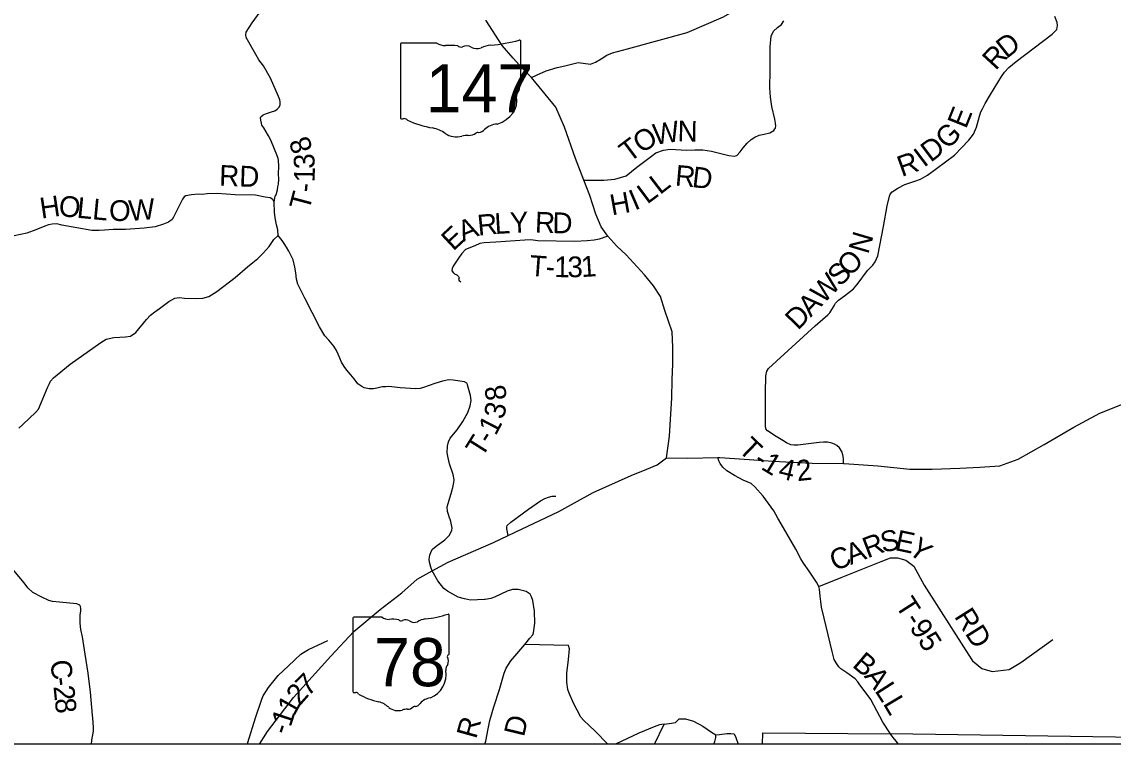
# Model space of a CAD drawing. Extents: x -22 to 431, y -18 to 160.
# Drawn here: x 327.228 to 330.215, y 147.68 to 149.657 of the extents above; entities that cross this region are included whole.
import ezdxf

# ---------------------------------------------------------------- set-up
doc = ezdxf.new("R2010")
doc.units = 0
for name, color, linetype in [('GM_X_Adjacent_County_Text', 7, 'Continuous'), ('GM_X_Airport_Location_Class_2', 7, 'Continuous'), ('GM_X_City_Street', 7, 'Continuous'), ('GM_X_City_Street_Text', 7, 'Continuous'), ('GM_X_County_Road', 7, 'Continuous'), ('GM_X_County_ROW', 7, 'Continuous'), ('GM_X_Major_River_Text', 7, 'Continuous'), ('GM_X_Minor_River_Text', 7, 'Continuous'), ('GM_X_Section', 7, 'Continuous')]:
    doc.layers.add(name, color=color, linetype=linetype)

msp = doc.modelspace()

# ---------------------------------------------------------------- linework, layer by layer
at = {"layer": 'GM_X_Adjacent_County_Text'}
for points in [[(327.2193, 148.5451), (327.2307, 148.5547), (327.266, 148.5891), (327.273, 148.597), (327.2809, 148.6148), (327.2985, 148.6585), (327.3031, 148.6676), (327.3065, 148.6733), (327.3142, 148.6825), (327.36, 148.7198), (327.444, 148.7799), (327.4586, 148.7886), (327.4799, 148.7933), (327.5119, 148.7948), (327.5251, 148.7968), (327.54, 148.8073), (327.5688, 148.8423), (327.5796, 148.854), (327.5916, 148.8636), (327.605, 148.8727), (327.6301, 148.8916), (327.6467, 148.901), (327.659, 148.9027), (327.6727, 148.9013), (327.7048, 148.8998), (327.7232, 148.9013), (327.7395, 148.9056), (327.762, 148.9188), (327.8116, 148.9579), (327.8455, 148.9866), (327.8599, 148.9989), (327.8735, 149.0092), (327.8889, 149.024), (327.9046, 149.0424), (327.9174, 149.0615), (327.9298, 149.0722), (327.9282, 149.0879), (327.9249, 149.1021), (327.9217, 149.1209), (327.9198, 149.1368), (327.9183, 149.1641), (327.9146, 149.171), (327.9077, 149.1755), (327.8935, 149.177), (327.8677, 149.1831), (327.8121, 149.1839), (327.7621, 149.1873), (327.7348, 149.1862), (327.7219, 149.185), (327.7116, 149.1858), (327.6927, 149.1842), (327.6764, 149.1812), (327.6722, 149.1782), (327.6673, 149.1721), (327.6555, 149.1482), (327.643, 149.1231), (327.6392, 149.1167), (327.629, 149.1094), (327.6154, 149.1034), (327.593, 149.0958), (327.5623, 149.0923), (327.5118, 149.0893), (327.4883, 149.0893), (327.4781, 149.0893), (327.4538, 149.087), (327.4394, 149.0858), (327.4197, 149.0866), (327.3374, 149.1006), (327.3237, 149.1048), (327.3112, 149.1036), (327.301, 149.1017), (327.2908, 149.0976), (327.2661, 149.0884), (327.2415, 149.0789), (327.1895, 149.0679)], [(329.6098, 147.7028), (329.6058, 147.708), (329.5852, 147.7406), (329.5519, 147.8018), (329.5203, 147.8449), (329.5165, 147.8506), (329.5093, 147.8586), (329.4861, 147.8753), (329.4698, 147.8859), (329.4641, 147.8916), (329.4569, 147.903), (329.452, 147.9117), (329.4459, 147.9337), (329.4239, 148.0252), (329.4174, 148.0548), (329.4155, 148.0703), (329.4132, 148.0855), (329.4117, 148.1045), (329.4093, 148.1117), (329.4037, 148.1234), (329.3836, 148.1534), (329.3681, 148.1758), (329.3605, 148.1876), (329.3468, 148.2137), (329.3127, 148.2722), (329.2975, 148.2984), (329.2918, 148.309), (329.2861, 148.3188), (329.2573, 148.3591), (329.2349, 148.3845), (329.2242, 148.3936), (329.2026, 148.4031), (329.1784, 148.4156), (329.1582, 148.4285), (329.1472, 148.4379), (329.1393, 148.4486), (329.1359, 148.4558), (329.1336, 148.465)], [(327.4211, 147.7596), (327.4211, 147.7597), (327.4161, 147.8221), (327.4096, 147.8741), (327.4012, 147.9261), (327.394, 147.9739), (327.3894, 147.9936), (327.3879, 148.0114), (327.3875, 148.0331), (327.389, 148.0452), (327.389, 148.0517), (327.3883, 148.0566), (327.3864, 148.0604), (327.3784, 148.0638), (327.331, 148.0687), (327.3121, 148.0706), (327.3018, 148.0737), (327.2821, 148.0824), (327.2582, 148.0949), (327.2438, 148.1082), (327.2339, 148.1214), (327.2055, 148.1556)], [(327.4185, 147.6799), (327.4191, 147.6912), (327.4241, 147.7154), (327.4244, 147.7265), (327.4218, 147.7507), (327.4211, 147.7596)], [(329.6276, 147.6799), (329.6248, 147.6834), (329.6098, 147.7028)]]:
    msp.add_lwpolyline(points, dxfattribs=at)
at = {"layer": 'GM_X_Airport_Location_Class_2'}
for p, q in [((328.3639, 149.599), (328.2674, 149.599)), ((328.5937, 149.4993), (328.5937, 149.604)), ((328.2641, 149.5955), (328.2641, 149.3954)), ((328.5937, 149.4993), (328.5937, 149.4993)), ((328.1342, 148.0245), (328.1342, 147.8244)), ((328.214, 148.0279), (328.1368, 148.0279)), ((328.3978, 147.9282), (328.3978, 148.0329)), ((328.3978, 147.9282), (328.3978, 147.9282))]:
    msp.add_line(p, q, dxfattribs=at)
for centre, radius, start, end in [((328.1372, 148.0249), 0.00305, 98.1301, 188.1301), ((328.2324, 148.0512), 0.0296, 231.6195, 271.1119), ((328.2422, 147.9156), 0.1064, 80.4867, 94.9883), ((328.2663, 148.026), 0.00855, 219.7921, 297.1024), ((328.2789, 148.0028), 0.0178, 54.4667, 119.1411), ((328.3018, 148.0346), 0.0214, 233.8562, 294.8282), ((328.3396, 147.9668), 0.0563, 97.3462, 120.7689), ((328.3039, 148.3008), 0.2796, 275.8445, 288.9065), ((328.3949, 148.0333), 0.00294, 351.8621, 97.738), ((328.3971, 147.9205), 0.00454, 107.944, 210.337), ((328.3947, 147.9278), 0.00314, 289.6038, 7.7341), ((328.4083, 147.8844), 0.0198, 136.8065, 186.9296), ((328.3683, 147.9073), 0.0273, 340.033, 23.6496), ((328.3196, 147.8711), 0.0699, 292.3089, 8.9858), ((328.1372, 147.8239), 0.00308, 171.9584, 258.3066), ((328.1377, 147.8444), 0.0235, 267.339, 280.6039), ((328.1425, 147.8128), 0.00848, 29.7484, 93.2717), ((328.2495, 147.9926), 0.2019, 240.4129, 257.1985), ((328.3491, 147.7682), 0.0383, 94.4031, 142.5768), ((328.1893, 147.7345), 0.0632, 47.1842, 75.836), ((328.2577, 147.8118), 0.0401, 230.7004, 286.2918), ((328.2808, 147.7427), 0.0329, 85.6951, 111.2099), ((328.2838, 147.7969), 0.0214, 268.777, 315.5493), ((328.3031, 147.7775), 0.00601, 65.7517, 132.6484), ((328.3005, 147.805), 0.0226, 282.8732, 323.2771)]:
    msp.add_arc(centre, radius, start, end, dxfattribs=at)
for centre, major_axis, start_param, end_param in [((328.2679, 149.596), (0.00382, 0), 1.712693, 3.28349), ((328.3869, 149.6222), (0.037, 0), 4.042523, 4.731795), ((328.4763, 149.8718), (0.3495, 0), 4.814394, 5.042369), ((328.5901, 149.6044), (0.00367, 0), 6.141152, 7.989035), ((328.3992, 149.4866), (0.133, 0), 1.404758, 1.657858), ((328.4294, 149.597), (0.0107, 0), 3.836095, 5.185415), ((328.445, 149.5739), (0.0222, 0), 0.950623, 2.079405), ((328.4737, 149.6056), (0.0267, 0), 4.081561, 5.145723), ((328.5209, 149.5379), (0.0703, 0), 1.699011, 2.107814), ((328.5929, 149.4916), (0.00568, 0), 1.883978, 3.671073), ((328.5568, 149.4783), (0.0341, 0), 5.934695, 6.695948), ((328.5898, 149.4989), (0.00393, 0), 5.05454, 6.418171), ((328.4959, 149.4421), (0.0874, 0), 5.101752, 6.440018), ((328.6069, 149.4555), (0.0248, 0), 2.387724, 3.262537), ((328.268, 149.395), (0.00385, 0), 3.00124, 4.508301), ((328.2685, 149.4155), (0.0294, 0), 4.665946, 4.897461), ((328.2746, 149.3839), (0.0106, 0), 0.519207, 1.627899), ((328.4084, 149.5637), (0.2524, 0), 4.195997, 4.488961), ((328.3331, 149.3055), (0.079, 0), 0.823519, 1.323587), ((328.4721, 149.376), (0.0282, 0), 4.937069, 5.64225), ((328.5328, 149.3392), (0.0479, 0), 1.647645, 2.488434), ((328.4185, 149.3829), (0.0501, 0), 4.026481, 4.996735), ((328.4475, 149.3137), (0.0412, 0), 1.495662, 1.94098), ((328.4512, 149.3679), (0.0267, 0), 4.691044, 5.507374), ((328.4753, 149.3485), (0.00752, 0), 1.147584, 2.315152)]:
    msp.add_ellipse(centre, major_axis=major_axis, ratio=0.8, start_param=start_param, end_param=end_param, dxfattribs=at)
at = {"layer": 'GM_X_County_Road'}
for points in [[(328.6233, 149.5046), (328.637, 149.5113), (328.6636, 149.5231), (328.6935, 149.5327), (328.7145, 149.5371), (328.7507, 149.546), (328.7844, 149.5418), (328.798, 149.5469), (328.8135, 149.5561), (328.8293, 149.5661), (328.8452, 149.5726), (328.8857, 149.5832), (329.0489, 149.6284), (329.1491, 149.6709), (329.2216, 149.7131), (329.2904, 149.7527), (329.419, 149.7935)], [(329.2913, 149.3779), (329.2912, 149.38), (329.2888, 149.3914), (329.281, 149.4258), (329.277, 149.4512), (329.2757, 149.477), (329.2761, 149.5245), (329.2764, 149.5886), (329.2789, 149.6179), (329.286, 149.632), (329.2969, 149.6416), (329.3078, 149.65), (329.3142, 149.6603)], [(329.8124, 147.9361), (329.8301, 147.9085), (329.8562, 147.8869), (329.8843, 147.8785), (329.9309, 147.8843), (329.9624, 147.9036), (330.0504, 147.9662)], [(329.1223, 147.6799), (329.1248, 147.6874), (329.1274, 147.6982), (329.1274, 147.7058)]]:
    msp.add_lwpolyline(points, dxfattribs=at)
at = {"layer": 'GM_X_County_ROW'}
for points in [[(328.9929, 148.4635), (329.0005, 148.523), (329.0032, 148.5694), (329.0073, 148.6271), (329.008, 148.6781), (329.0104, 148.7202), (329.0101, 148.7666), (329.0079, 148.8091), (328.9885, 148.8676), (328.9759, 148.9051), (328.9566, 148.9345), (328.9321, 148.9649), (328.8822, 149.0197), (328.8563, 149.043), (328.8317, 149.0708), (328.8134, 149.0964), (328.7991, 149.1306), (328.7828, 149.1816), (328.7662, 149.2237), (328.7437, 149.2835), (328.7138, 149.3691), (328.6898, 149.4241), (328.6233, 149.5046), (328.5986, 149.5301), (328.5731, 149.5578), (328.5424, 149.593), (328.4983, 149.6623)], [(328.9929, 148.4635), (329.0504, 148.463), (329.1336, 148.465), (329.1384, 148.4651), (329.2187, 148.4592), (329.284, 148.4549), (329.3916, 148.4489), (329.477, 148.4481), (329.4793, 148.448), (329.5709, 148.4415), (329.6588, 148.433), (329.7195, 148.4332), (329.7958, 148.4355), (329.8508, 148.4386), (329.9055, 148.4422), (329.9553, 148.4604), (330.0269, 148.4999), (330.1078, 148.5479), (330.179, 148.5862), (330.2413, 148.6111)], [(327.8786, 147.6799), (327.9005, 147.7149), (327.9712, 147.8079), (328.0735, 147.9207), (328.1363, 147.9882), (328.2091, 148.0482), (328.2684, 148.0946), (328.31, 148.1314), (328.3508, 148.1541), (328.3951, 148.1786), (328.5192, 148.2322), (328.5591, 148.2512), (328.5957, 148.2687), (328.6983, 148.317), (328.7921, 148.369), (328.8962, 148.415), (328.9388, 148.4332), (328.9671, 148.445), (328.9929, 148.4635)]]:
    msp.add_lwpolyline(points, dxfattribs=at)
at = {"layer": 'GM_X_Major_River_Text'}
for p, q in [((329.2558, 147.6799), (329.2561, 147.7112)), ((329.2561, 147.7112), (329.6058, 147.708)), ((331.1607, 147.6846), (329.6058, 147.708))]:
    msp.add_line(p, q, dxfattribs=at)
at = {"layer": 'GM_X_Minor_River_Text'}
for points in [[(327.9183, 149.1641), (327.9215, 149.1799), (327.9236, 149.1836), (327.9278, 149.1972), (327.9289, 149.2056), (327.9304, 149.2127), (327.9309, 149.2264), (327.9305, 149.2415), (327.9313, 149.2615), (327.9308, 149.2788), (327.9295, 149.2837), (327.9263, 149.2936), (327.9196, 149.3086), (327.9095, 149.3337), (327.9029, 149.3457), (327.8899, 149.3673), (327.8851, 149.3749), (327.8837, 149.3797), (327.8817, 149.3886), (327.8815, 149.3947), (327.8824, 149.3977), (327.8889, 149.4024), (327.898, 149.4065), (327.9114, 149.4114), (327.9203, 149.414), (327.9271, 149.418), (327.9326, 149.4237), (327.9353, 149.4299), (327.9354, 149.4383), (327.9343, 149.4441), (327.9308, 149.4534), (327.9086, 149.5029), (327.8897, 149.5367), (327.8766, 149.5533), (327.8687, 149.568), (327.8423, 149.6147), (327.8408, 149.6215), (327.8419, 149.6287), (327.8586, 149.6546), (327.9119, 149.7295)], [(329.2932, 148.5225), (329.2692, 148.5376), (329.265, 148.5436), (329.2638, 148.5516), (329.2639, 148.6416), (329.2644, 148.6886), (329.2673, 148.7008), (329.2722, 148.7084), (329.2937, 148.7283), (329.3996, 148.8251), (329.4342, 148.8557), (329.4395, 148.861), (329.4526, 148.8816), (329.4556, 148.887), (329.4635, 148.8954), (329.4798, 148.9073), (329.5043, 148.9268), (329.5133, 148.9371), (329.5227, 148.9497), (329.5347, 148.9661), (329.5441, 148.9776), (329.5573, 148.9913), (329.5641, 149.0001), (329.5708, 149.0168), (329.5869, 149.0967), (329.5967, 149.1537), (329.603, 149.1803), (329.6052, 149.1856), (329.6105, 149.1921), (329.6256, 149.2017), (329.6452, 149.2117), (329.6532, 149.2152), (329.6728, 149.2214), (329.688, 149.2268), (329.7072, 149.238), (329.7808, 149.2924), (329.8207, 149.3333), (329.8328, 149.3501), (329.8417, 149.3695), (329.8498, 149.3992), (329.8536, 149.4106), (329.8573, 149.4193), (329.8648, 149.4334), (329.8798, 149.4586), (329.9101, 149.5074), (329.9184, 149.5192), (329.9301, 149.5322), (329.9497, 149.5491), (330.0485, 149.6238), (330.0609, 149.6368), (330.0628, 149.6478), (330.0623, 149.6554), (330.0561, 149.6717)], [(328.7662, 149.2237), (328.8212, 149.2244), (328.8508, 149.2263), (328.8826, 149.2362), (328.9112, 149.2596), (328.952, 149.2899), (328.9637, 149.2987), (328.9845, 149.3057), (329.0023, 149.3084), (329.0474, 149.3065), (329.0698, 149.3067), (329.0918, 149.3072), (329.1154, 149.3036), (329.1636, 149.2918), (329.1784, 149.2896), (329.1852, 149.2919), (329.1943, 149.3011), (329.2022, 149.3129), (329.2131, 149.3251), (329.224, 149.3351), (329.2342, 149.342), (329.2463, 149.347), (329.2596, 149.3501), (329.2758, 149.3533), (329.2868, 149.3598), (329.2894, 149.3641), (329.2909, 149.3667), (329.2916, 149.3735), (329.2913, 149.3779)], [(328.4051, 148.3739), (328.4078, 148.383), (328.4105, 148.3963), (328.4112, 148.4039), (328.4082, 148.4179), (328.3987, 148.4475), (328.3945, 148.4642), (328.3919, 148.4779), (328.393, 148.4957), (328.396, 148.5078), (328.4006, 148.5177), (328.4195, 148.5405), (328.435, 148.5633), (328.4487, 148.5876), (328.4551, 148.6061), (328.4578, 148.621), (328.4559, 148.6342), (328.449, 148.6597), (328.4475, 148.665), (328.446, 148.668), (328.4392, 148.6722), (328.4088, 148.6763), (328.3971, 148.6771), (328.3796, 148.6741), (328.3588, 148.6672), (328.3277, 148.6562), (328.3182, 148.6535), (328.3065, 148.6531), (328.2632, 148.655), (328.2409, 148.6581), (328.2321, 148.6588), (328.2242, 148.6584), (328.2143, 148.658), (328.1995, 148.6542), (328.1908, 148.6527), (328.1787, 148.6527), (328.1654, 148.6558), (328.1582, 148.6595), (328.1472, 148.6668), (328.1373, 148.68), (328.1286, 148.6914), (328.1176, 148.7036), (328.1104, 148.7142), (328.1028, 148.7259), (328.0941, 148.7476), (328.0891, 148.7574), (328.0823, 148.7696), (328.0679, 148.7863), (328.0576, 148.7976), (328.0428, 148.8227), (328.0022, 148.9012), (327.9886, 148.9282), (327.9836, 148.9388), (327.9798, 148.9525), (327.9778, 148.9704), (327.9755, 148.9862), (327.9703, 149.0057), (327.9587, 149.0296), (327.9519, 149.0407), (327.9461, 149.0505), (327.9403, 149.0587), (327.9298, 149.0722)], [(328.8317, 149.0708), (328.8087, 149.0626), (328.7947, 149.0597), (328.7757, 149.0579), (328.7419, 149.0565), (328.6403, 149.0583), (328.6209, 149.0607), (328.6045, 149.0594), (328.5256, 149.0539), (328.4939, 149.0528), (328.4819, 149.0505), (328.4681, 149.0441), (328.4421, 149.0338), (328.4323, 149.0236), (328.4248, 149.0132), (328.4089, 148.9888), (328.4055, 148.9818), (328.4053, 148.9757), (328.4082, 148.971), (328.4122, 148.9673), (328.4182, 148.9651), (328.4236, 148.9606), (328.4249, 148.9567), (328.4235, 148.9524), (328.4251, 148.9493), (328.4292, 148.9452)], [(329.477, 148.4481), (329.4773, 148.462), (329.4753, 148.4719), (329.4722, 148.4814), (329.4665, 148.4908), (329.4588, 148.498), (329.4524, 148.5013), (329.4451, 148.5043), (329.4333, 148.5069), (329.422, 148.5064), (329.4102, 148.5056), (329.3518, 148.4987), (329.3412, 148.4986), (329.3329, 148.4993), (329.3215, 148.5046), (329.3107, 148.5114), (329.2932, 148.5225)], [(328.3999, 148.297), (328.395, 148.3112), (328.3927, 148.3173), (328.3919, 148.3295), (328.3972, 148.3481), (328.4047, 148.3726), (328.4051, 148.3739)], [(328.5591, 148.2512), (328.5558, 148.2694), (328.5554, 148.2751), (328.5565, 148.2785), (328.5663, 148.288), (328.6152, 148.3234), (328.6481, 148.3459), (328.6598, 148.3523), (328.6697, 148.3565), (328.6795, 148.3588), (328.6898, 148.3592)], [(328.4944, 148.0756), (328.4942, 148.0756), (328.4565, 148.0745), (328.4398, 148.0779), (328.4224, 148.0824), (328.3932, 148.0987), (328.3833, 148.1063), (328.3662, 148.1272), (328.3508, 148.1541), (328.3476, 148.1644), (328.3438, 148.1784), (328.3431, 148.186), (328.3446, 148.1974), (328.348, 148.2072), (328.3522, 148.2141), (328.362, 148.2221), (328.3859, 148.2395), (328.3984, 148.2524), (328.4052, 148.2657), (328.4056, 148.2714), (328.4026, 148.2892), (328.4002, 148.2959), (328.3999, 148.297)], [(329.471, 148.1362), (329.4711, 148.1363), (329.5804, 148.1797), (329.6062, 148.19), (329.6252, 148.19), (329.6475, 148.1839), (329.6695, 148.1676), (329.698, 148.1153), (329.8122, 147.9364), (329.8124, 147.9361)], [(329.4093, 148.1117), (329.471, 148.1362)], [(328.6052, 147.9527), (328.6181, 147.9702), (328.6264, 147.9789), (328.6283, 147.985), (328.6321, 148.0108), (328.6317, 148.0442), (328.6268, 148.073), (328.6226, 148.0836), (328.6192, 148.0905), (328.6089, 148.0977), (328.5869, 148.1034), (328.5714, 148.103), (328.5562, 148.0984), (328.5391, 148.0908), (328.5217, 148.0825), (328.5115, 148.0787), (328.4963, 148.0756), (328.4944, 148.0756)], [(327.8456, 147.6799), (327.8465, 147.6841), (327.8677, 147.7517), (327.8848, 147.8029), (327.8886, 147.8124), (327.9033, 147.8348), (327.9299, 147.8678), (327.9575, 147.8948), (327.9913, 147.9259), (327.9985, 147.9312), (328.0121, 147.9392), (328.0652, 147.9635)], [(328.4953, 147.6799), (328.4984, 147.6878), (328.5044, 147.7219), (328.5086, 147.7443), (328.5203, 147.7823), (328.5351, 147.8293), (328.5483, 147.8745), (328.5533, 147.8882), (328.5662, 147.9083), (328.6052, 147.9527)], [(328.7485, 147.7731), (328.7484, 147.7732), (328.7384, 147.7926), (328.7258, 147.8195), (328.7228, 147.8298), (328.7198, 147.8499), (328.7197, 147.8742), (328.7243, 147.9114), (328.7269, 147.941), (328.7243, 147.9501), (328.6052, 147.9527)], [(328.8324, 147.6799), (328.7972, 147.7156), (328.7653, 147.7459), (328.7585, 147.7539), (328.7485, 147.7731)], [(328.986, 147.7346), (329.0065, 147.7377), (329.0171, 147.7396), (329.0272, 147.7489), (329.0445, 147.7494), (329.0668, 147.7428), (329.0918, 147.7294), (329.1159, 147.7124), (329.1274, 147.7058), (329.1381, 147.7068), (329.1574, 147.7087), (329.1686, 147.709), (329.1778, 147.7079), (329.1827, 147.6981), (329.1888, 147.6799)], [(328.9601, 147.6799), (328.986, 147.7346), (328.9735, 147.7327), (328.9591, 147.7278), (328.917, 147.7099), (328.8527, 147.6799)]]:
    msp.add_lwpolyline(points, dxfattribs=at)
at = {"layer": 'GM_X_Section'}
msp.add_line((331.7949, 147.6799), (319.5549, 147.6799), dxfattribs=at)

# ---------------------------------------------------------------- texts
at = {"layer": 'GM_X_Airport_Location_Class_2'}
for s, p in [('147', (328.3336, 149.4095)), ('78', (328.1923, 147.8385))]:
    msp.add_text(s, height=0.13184, dxfattribs=at).set_placement(p)
at = {"layer": 'GM_X_City_Street'}
for s, height, rotation, p in [('RD', 0.05682, 358.0243, (327.7673, 149.2088)), ('H', 0.0568, 8.5191, (327.2813, 149.1185)), ('O', 0.0568, 354.8643, (327.3272, 149.1258)), ('L', 0.0568, 354.4459, (327.3769, 149.1213)), ('L', 0.0568, 354.6233, (327.4193, 149.1172)), ('O', 0.0568, 358.5718, (327.4659, 149.113)), ('W', 0.0568, 4.7606, (327.5226, 149.1119)), ('B', 0.0568, 319.5668, (329.4987, 147.8936)), ('C', 0.0568, 278.1533, (327.3048, 147.9072)), ('A', 0.0568, 306.7468, (329.5319, 147.8658)), ('2', 0.0568, 276.0741, (327.3141, 147.8384)), ('-', 0.0568, 276.7445, (327.3114, 147.8614)), ('L', 0.0568, 302.7795, (329.5612, 147.8265)), ('8', 0.0568, 275.8126, (327.3178, 147.8037)), ('L', 0.0568, 300.8219, (329.5839, 147.7912))]:
    msp.add_text(s, height=height, rotation=rotation, dxfattribs=at).set_placement(p)
at = {"layer": 'GM_X_City_Street_Text'}
for s, height, rotation, p in [('D', 0.0568, 38.2667, (329.9236, 149.5551)), ('R', 0.0568, 47.4459, (329.8938, 149.5224)), ('E', 0.0568, 68.2368, (329.8125, 149.3625)), ('W', 0.0568, 8.5726, (328.9599, 149.3204)), ('O', 0.0568, 32.6595, (328.9237, 149.2956)), ('N', 0.0568, 359.1257, (329.0226, 149.3301)), ('G', 0.0568, 43.9398, (329.7619, 149.3061)), ('8', 0.0568, 109.5363, (328.025, 149.3091)), ('T', 0.0568, 36.7962, (328.8906, 149.2708)), ('D', 0.0568, 36.7235, (329.7158, 149.2712)), ('R', 0.0568, 19.4989, (329.6366, 149.2325)), ('I', 0.0568, 37.2136, (329.6974, 149.2572)), ('3', 0.0568, 92.3735, (328.03, 149.2559)), ('1', 0.0568, 89.1691, (328.0295, 149.2175)), ('R', 0.0568, 354.8568, (329.0147, 149.2094)), ('D', 0.0568, 353.2599, (329.0608, 149.2053)), ('-', 0.0568, 83.9932, (328.0267, 149.1887)), ('L', 0.0568, 36.6896, (328.9397, 149.1567)), ('L', 0.0568, 37.5359, (328.9745, 149.1826)), ('T', 0.0568, 75.0813, (328.0141, 149.1382)), ('H', 0.0568, 10.2547, (328.8431, 149.1273)), ('I', 0.0568, 23.1463, (328.9056, 149.1402)), ('R', 0.0568, 5.704, (328.4776, 149.0718)), ('L', 0.0568, 3.4004, (328.5234, 149.0764)), ('Y', 0.0568, 2.941, (328.5657, 149.079)), ('R', 0.0568, 357.6106, (328.6317, 149.081)), ('D', 0.0568, 359.1798, (328.6801, 149.079)), ('E', 0.0568, 42.954, (328.4088, 149.0282)), ('A', 0.0568, 21.8745, (328.4353, 149.0542)), ('N', 0.0568, 73.6017, (329.5445, 149.0194)), ('O', 0.0568, 45.9149, (329.4947, 148.9579)), ('T', 0.0568, 355.8393, (328.6159, 148.9623)), ('1', 0.0568, 359.1101, (328.6852, 148.9587)), ('3', 0.0568, 0.4459, (328.7216, 148.9581)), ('1', 0.0568, 3.624, (328.7601, 148.9585)), ('-', 0.0568, 359.1336, (328.6619, 148.959)), ('W', 0.0568, 45.8812, (329.4222, 148.8831)), ('S', 0.0568, 45.8803, (329.468, 148.9303)), ('A', 0.0568, 45.8776, (329.3874, 148.8472)), ('D', 0.0568, 45.8784, (329.3526, 148.8113)), ('8', 0.0568, 98.0334, (328.5559, 148.6246)), ('3', 0.0568, 76.1123, (328.5463, 148.5671)), ('1', 0.0568, 62.7286, (328.5252, 148.5225)), ('T', 0.0568, 57.847, (328.4875, 148.4621)), ('-', 0.0568, 57.7671, (328.5101, 148.4981)), ('T', 0.0568, 316.1031, (329.1865, 148.4845)), ('-', 0.0568, 329.3612, (329.2285, 148.4463)), ('1', 0.0568, 328.9363, (329.2485, 148.4345)), ('4', 0.0568, 346.5596, (329.296, 148.4093)), ('2', 0.0568, 6.1717, (329.3511, 148.3998)), ('R', 0.0568, 20.7831, (329.5429, 148.1882)), ('S', 0.0568, 11.4078, (329.5842, 148.2041)), ('E', 0.0568, 348.0639, (329.6157, 148.2117)), ('A', 0.0568, 21.2284, (329.4964, 148.1701)), ('Y', 0.0568, 321.8784, (329.6511, 148.2058)), ('C', 0.0568, 21.2303, (329.4529, 148.1532)), ('T-95', 0.05682, 302.6071, (329.6177, 148.0599)), ('RD', 0.05682, 302.3199, (329.779, 148.0296)), ('7', 0.0568, 44.3192, (328.0109, 147.8089)), ('2', 0.0568, 48.4944, (327.9885, 147.7834)), ('1', 0.0568, 60.767, (327.9733, 147.7555)), ('1', 0.0568, 71.6621, (327.9634, 147.7249)), ('R', 0.0568, 74.5488, (328.4715, 147.6924)), ('D', 0.0568, 76.4236, (328.6021, 147.698)), ('-', 0.0568, 72.1328, (327.9563, 147.7028))]:
    msp.add_text(s, height=height, rotation=rotation, dxfattribs=at).set_placement(p)

doc.saveas('drawing.dxf')
